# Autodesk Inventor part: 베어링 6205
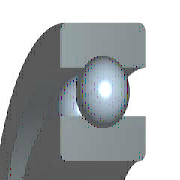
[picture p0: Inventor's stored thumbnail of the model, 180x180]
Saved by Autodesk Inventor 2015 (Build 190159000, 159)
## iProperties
Created: 2015-10
Part Number: 베어링 6205
Material: Steel, Mild
Description: 깊은 그루브 볼 베어링
Document SubType Name: Modeling
Standard: KS B 2023
Designer: mdu
Standards Organization: KS
Language: ko-KR
Size Designation: 6205 - 25 x 52 x 15
Categories: <MemberInstance><Categories><Category DisplayName="샤프트 부품" InternalName="7f7aeb1f-a693-4053-b835-cee3144e0d98" Mnemonic="SHFT"><Category DisplayName="베어링" Inter
Density: 1 g/cm^3
Appearance: Steel
IsCustomPart: 1
Author: mdu
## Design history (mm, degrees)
revolve "본체" stored, may be unused: angle "d6" = 90 deg
revolve "볼" stored, may be unused: angle "d7" = 90 deg
pattern_circular "IDS_ARRAYBALL[SIMPL:T]" dims angle "d3" = 360 deg
body "Solid1"
sketch "스케치" dims "d0" = 7.02 (= -0.26 x WD + 0.26 x BD)
  geometry: L1 (3.99, 19.25)-(11.01, 19.25); L2 (7.5, 19.25)-(7.5, 15.74); L3 (7.5, 19.25)-(7.5, 22.76); L4 (4.892, 16.901)-(0, 16.901); L5 (0, 12.5)-(15, 12.5); L6 (4.892, 21.599)-(0, 21.599); L7 (0, 26)-(15, 26); L8 (15, 12.5)-(15, 16.901); L9 (10.108, 16.901)-(15, 16.901); L10 (10.108, 21.599)-(15, 21.599); L11 (15, 26)-(15, 21.599); L12 (-1.4, 0)-(8.4, 0) reference; L13 (0, -0.3)-(0, 5.3) reference
  constraints: 22 end point, 4 point on line, 2 collinear, 2 perpendicular, 2 symmetric about line, 1 midpoint, 1 parallel, 14 other
  dimensions: "d9" = 25 diameter of L5 L12 (= WD); "d11" = 52 diameter of L7 L12 (= BD); "d12" = 15 distance between parallel lines of L8 L13 (= KB); "d13" = 33.802 diameter of L9 L12 (= 0.326 x BD + 0.674 x WD)
fillet "모깎기1" dims "d1" = 1 (= KRS)
other parameters: "WD" = 25 [user parameter; used in 5 equation terms], "BD" = 52 [user parameter; used in 5 equation terms], "KB" = 15 [user parameter; used in 1 equation term], "KRS" = 1 [user parameter; used in 1 equation term], "d4" = 0, "d5" = 0, "d8" = 0, "d14" = 0, "d15" = 0, "BBA" = 0 [user parameter], "BC0" = 7800000 [user parameter], "BC" = 1.4e+07 [user parameter], "BR" = 26 (= 0.5 x BD) [user parameter], "WR" = 12.5 (= 0.5 x WD) [user parameter]
